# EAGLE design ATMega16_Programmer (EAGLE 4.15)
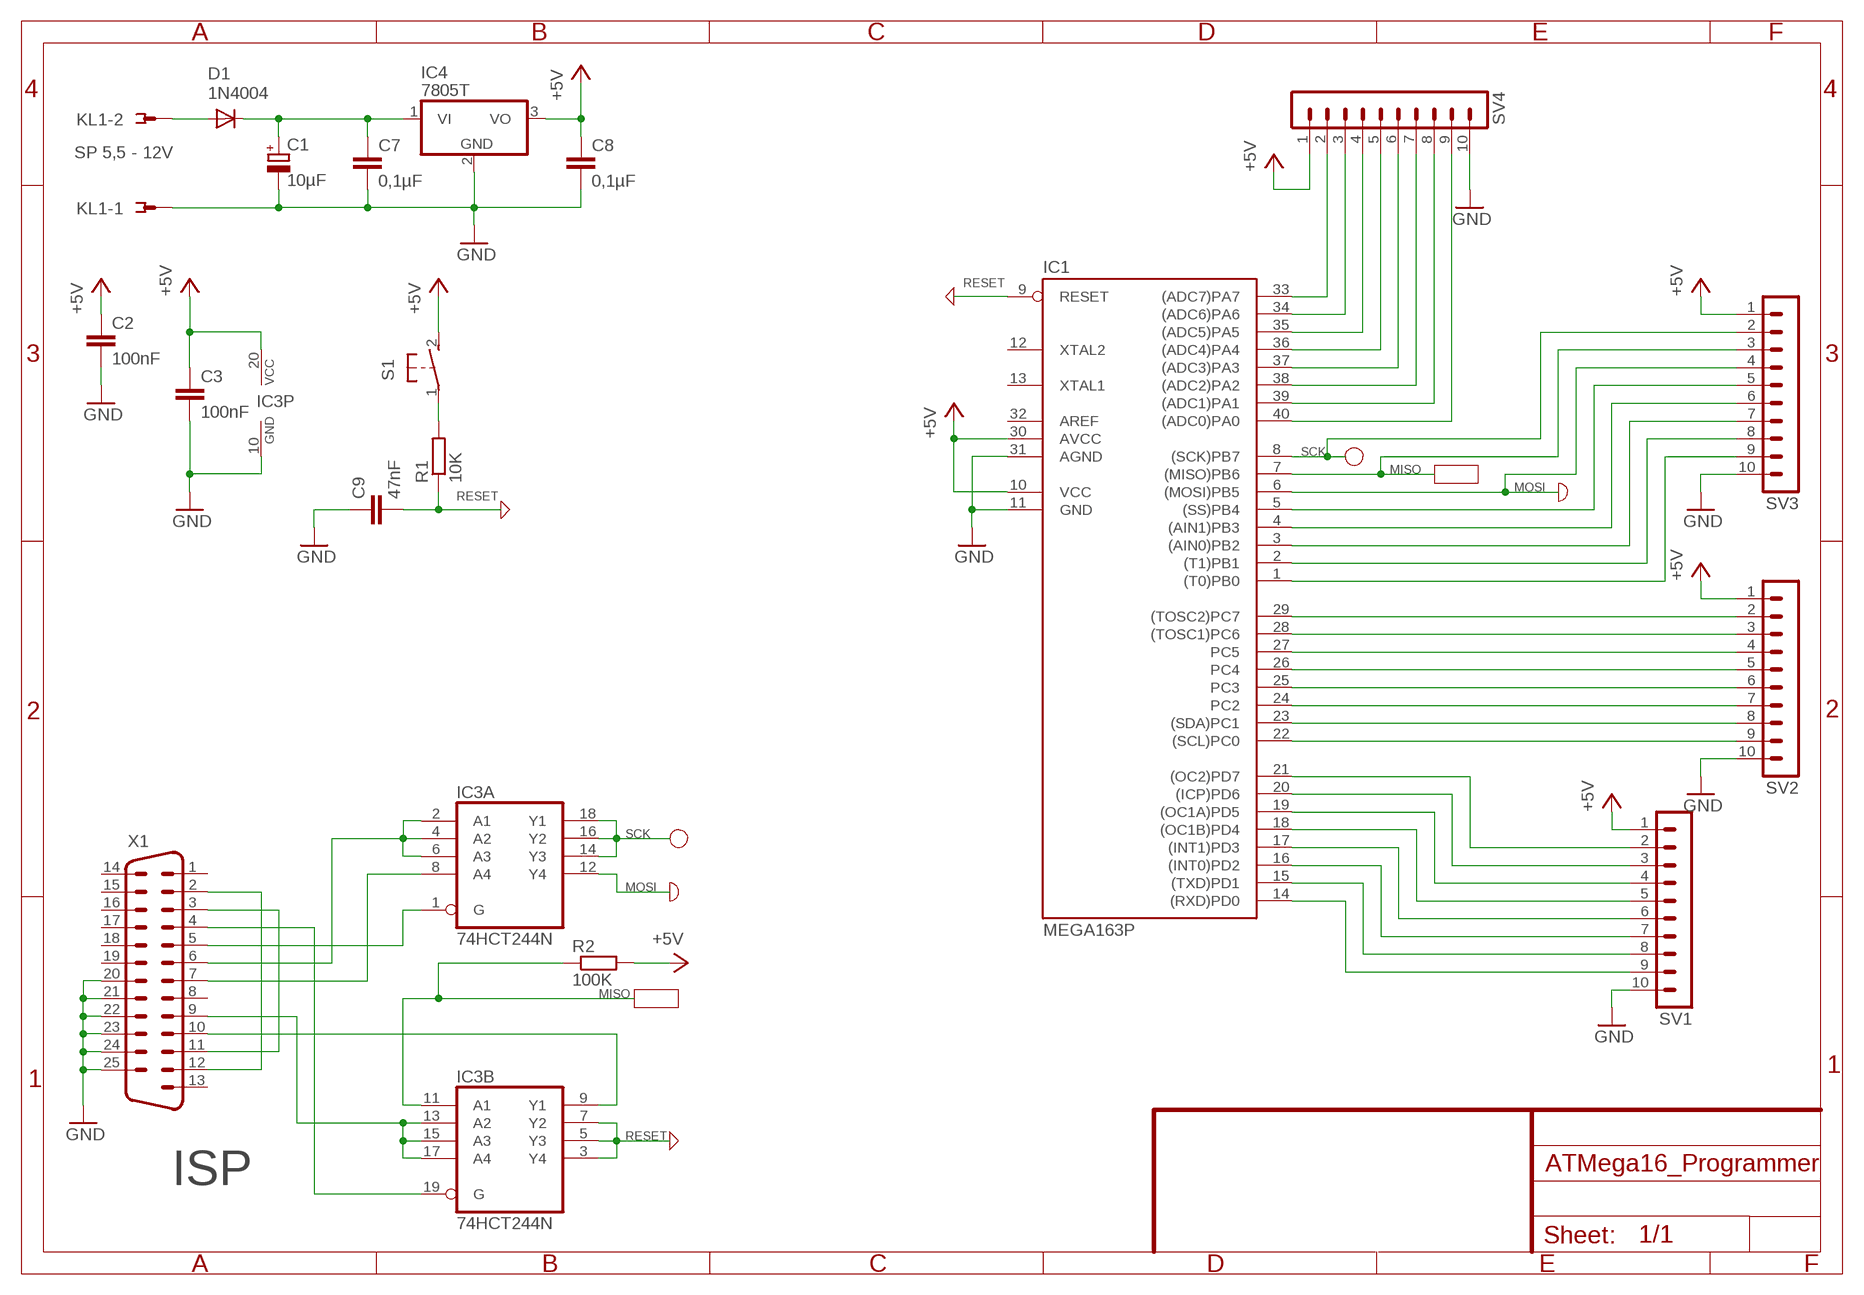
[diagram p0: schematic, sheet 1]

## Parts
C1  10µF  CPOL-EU  [E2-4-RASTERMAß!]
C2  100nF  C-EU050-025X075  [C050-025X075]
C3  100nF  C-EU050-025X075  [C050-025X075]
C7  0,1µF  C-EU050-025X075  [C050-025X075]
C8  0,1µF  C-EU050-025X075  [C050-025X075]
C9  47nF  C-EU050-025X075  [C050-025X075]
D1  1N4004  [DO41-10]
IC1  MEGA163P  [DIL40]
IC3  74HCT244N  [DIL20]
IC4  7805T  [TO220H]
KL1  SP 5,5 - 12V  2POL-PHOENIXSCHRAUBKLEMME  [PHOENIXSCHRAUBKLEMME2POL]
R1  10K  R-EU_0207/15  [0207/15]
R2  100K  R-EU_0207/12  [0207/12]
S1  31-XX  [B3F-31XX]
SV1  MA10-1  [MA10-1]
SV2  MA10-1  [MA10-1]
SV3  MA10-1  [MA10-1]
SV4  MA10-1  [MA10-1]
X1  M25HP  [M25HP]

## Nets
GND: C1.K-(-) C2.2 C3.2 C7.2 C8.2 C9.1 IC1.11(GND) IC1.31(AGND) IC3.10(P:GND) IC4.2(GND) KL1.P1 SV1.10 SV2.10 SV3.10 SV4.10 X1.20 X1.21 X1.22 X1.23 X1.24 X1.25
MISO: IC1.7((MISO)PB6) IC3.11(B:A1) R2.1 SV3.3
MOSI: IC1.6((MOSI)PB5) IC3.12(A:Y4) SV3.4
N$1: C1.K+(+) C7.1 D1.C IC4.1(VI)
N$2: D1.A KL1.P2
N$3: R1.2 S1.1(P)
N$5: X1.2 X1.12
N$6: X1.3 X1.11
N$7: IC3.9(B:Y1) X1.10
N$9: IC3.13(B:A2) IC3.15(B:A3) IC3.17(B:A4) X1.9
N$10: IC3.8(A:A4) X1.7
N$11: IC3.2(A:A1) IC3.4(A:A2) IC3.6(A:A3) X1.6
N$12: IC3.1(A:G) X1.5
N$13: IC3.19(B:G) X1.4
N$15: IC1.21((OC2)PD7) SV1.2
N$16: IC1.20((ICP)PD6) SV1.3
N$17: IC1.19((OC1A)PD5) SV1.4
N$18: IC1.18((OC1B)PD4) SV1.5
N$19: IC1.17((INT1)PD3) SV1.6
N$20: IC1.16((INT0)PD2) SV1.7
N$21: IC1.15((TXD)PD1) SV1.8
N$22: IC1.14((RXD)PD0) SV1.9
N$23: IC1.22((SCL)PC0) SV2.9
N$24: IC1.23((SDA)PC1) SV2.8
N$25: IC1.24(PC2) SV2.7
N$26: IC1.25(PC3) SV2.6
N$27: IC1.26(PC4) SV2.5
N$28: IC1.27(PC5) SV2.4
N$29: IC1.28((TOSC1)PC6) SV2.3
N$30: IC1.29((TOSC2)PC7) SV2.2
N$31: IC1.33((ADC7)PA7) SV4.2
N$32: IC1.34((ADC6)PA6) SV4.3
N$33: IC1.35((ADC5)PA5) SV4.4
N$34: IC1.36((ADC4)PA4) SV4.5
N$35: IC1.37((ADC3)PA3) SV4.6
N$36: IC1.38((ADC2)PA2) SV4.7
N$37: IC1.39((ADC1)PA1) SV4.8
N$38: IC1.40((ADC0)PA0) SV4.9
N$40: IC1.5((SS)PB4) SV3.5
N$41: IC1.4((AIN1)PB3) SV3.6
N$42: IC1.3((AIN0)PB2) SV3.7
N$43: IC1.2((T1)PB1) SV3.8
N$44: IC1.1((T0)PB0) SV3.9
RESET: C9.2 IC1.9(RESET) IC3.3(B:Y4) IC3.5(B:Y3) IC3.7(B:Y2) R1.1
SCK: IC1.8((SCK)PB7) IC3.14(A:Y3) IC3.16(A:Y2) IC3.18(A:Y1) SV3.2
VCC: C2.1 C3.1 C8.1 IC1.10(VCC) IC1.30(AVCC) IC3.20(P:VCC) IC4.3(VO) R2.2 S1.2(S) SV1.1 SV2.1 SV3.1 SV4.1 ; supply symbol labelled +5V
Unconnected: IC1.12(XTAL2) IC1.13(XTAL1) X1.1 X1.8 X1.13 X1.14 X1.15 X1.16 X1.17 X1.18 X1.19 X1.G1 X1.G2

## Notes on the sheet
- RESET
- SCK
- MISO
- MOSI
- RESET
- SCK
- MOSI
- MISO
- RESET
- ISP

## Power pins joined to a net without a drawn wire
AREF: IC1.32(AREF)

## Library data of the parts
C1 = rcl:CPOL-EU: POLARIZED CAPACITOR, European symbol
C2 C3 C7-C9 = rcl:C-EU: CAPACITOR, European symbol
D1 = diode:1N4004: DIODE
IC1 = atmel:MEGA163*P: MICROCONTROLLER 16 Kbytes FLASH, 1 Kbytes EEPROM 1 Kbytes SRAM UART 8-channel 10 bit ADC hardware multiplier
IC3 = 74xx-eu:74*244: Octal BUFFER and LINE DRIVER, 3-state
IC4 = linear:78*: Positive VOLTAGE REGULATOR Source: http://cache.national.com/ds/LM/LM78L05.pdf http://www.fairchildsemi.com/ds/LM/LM7805.pdf
KL1 = Swissphone_Standartbauteile:2POL-PHOENIXSCHRAUBKLEMME
R1 R2 = rcl:R-EU_: RESISTOR, European symbol
S1 = switch-omron:31-XX: OMRON SWITCH
SV1-SV4 = con-lstb:MA10-1: PIN HEADER
X1 = con-subd:M25HP: SUB-D

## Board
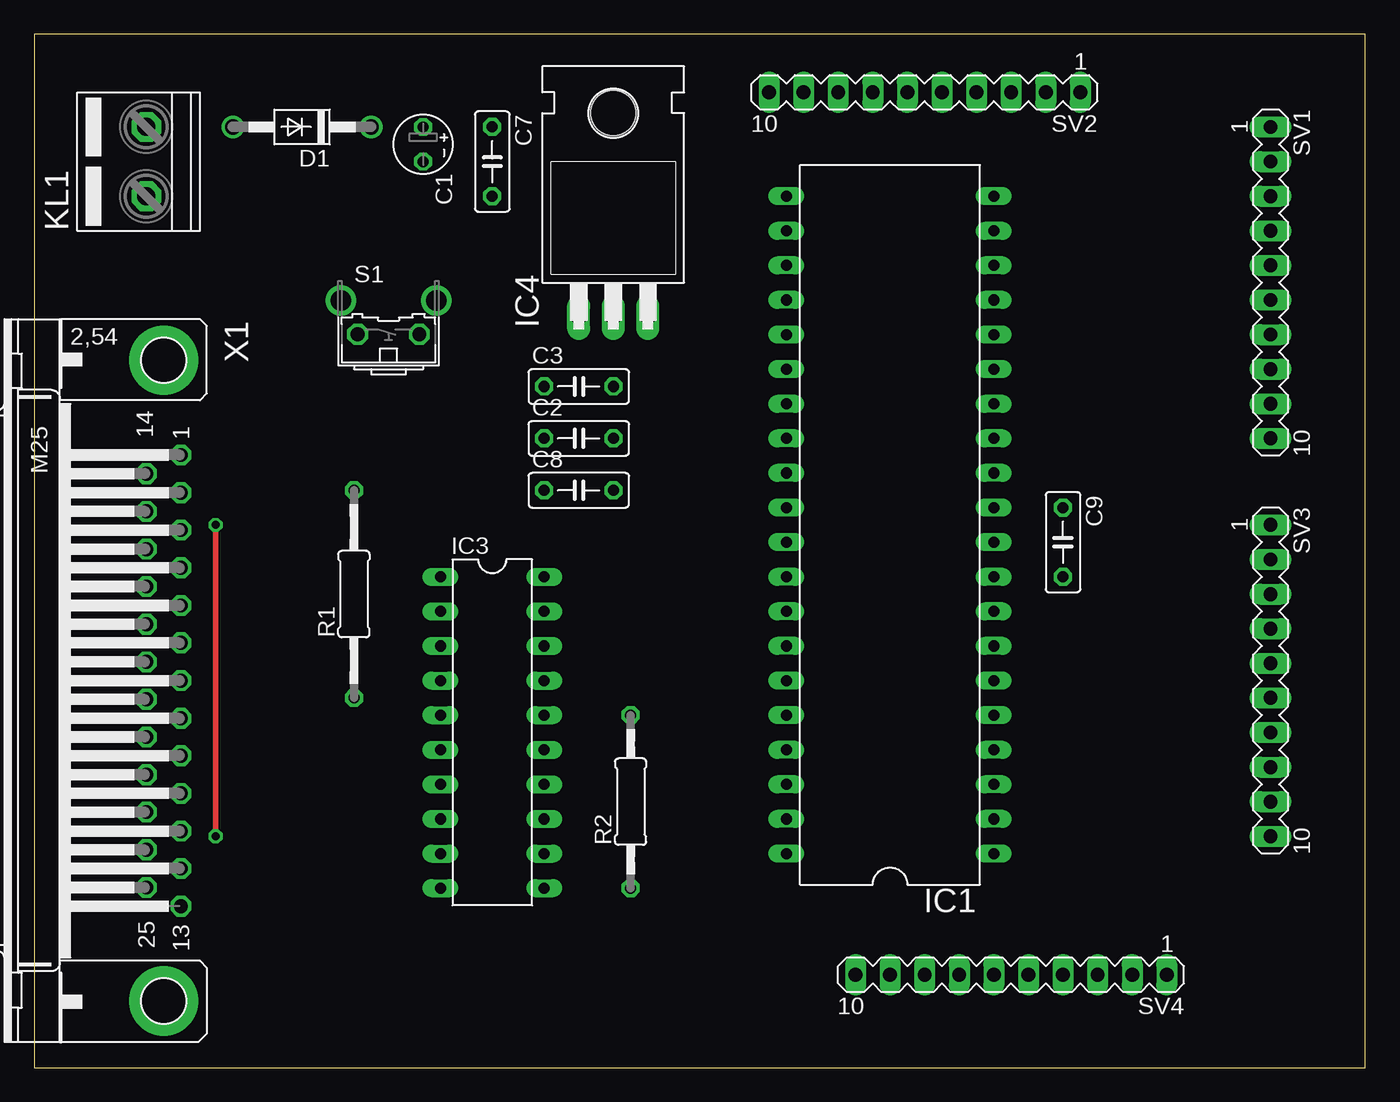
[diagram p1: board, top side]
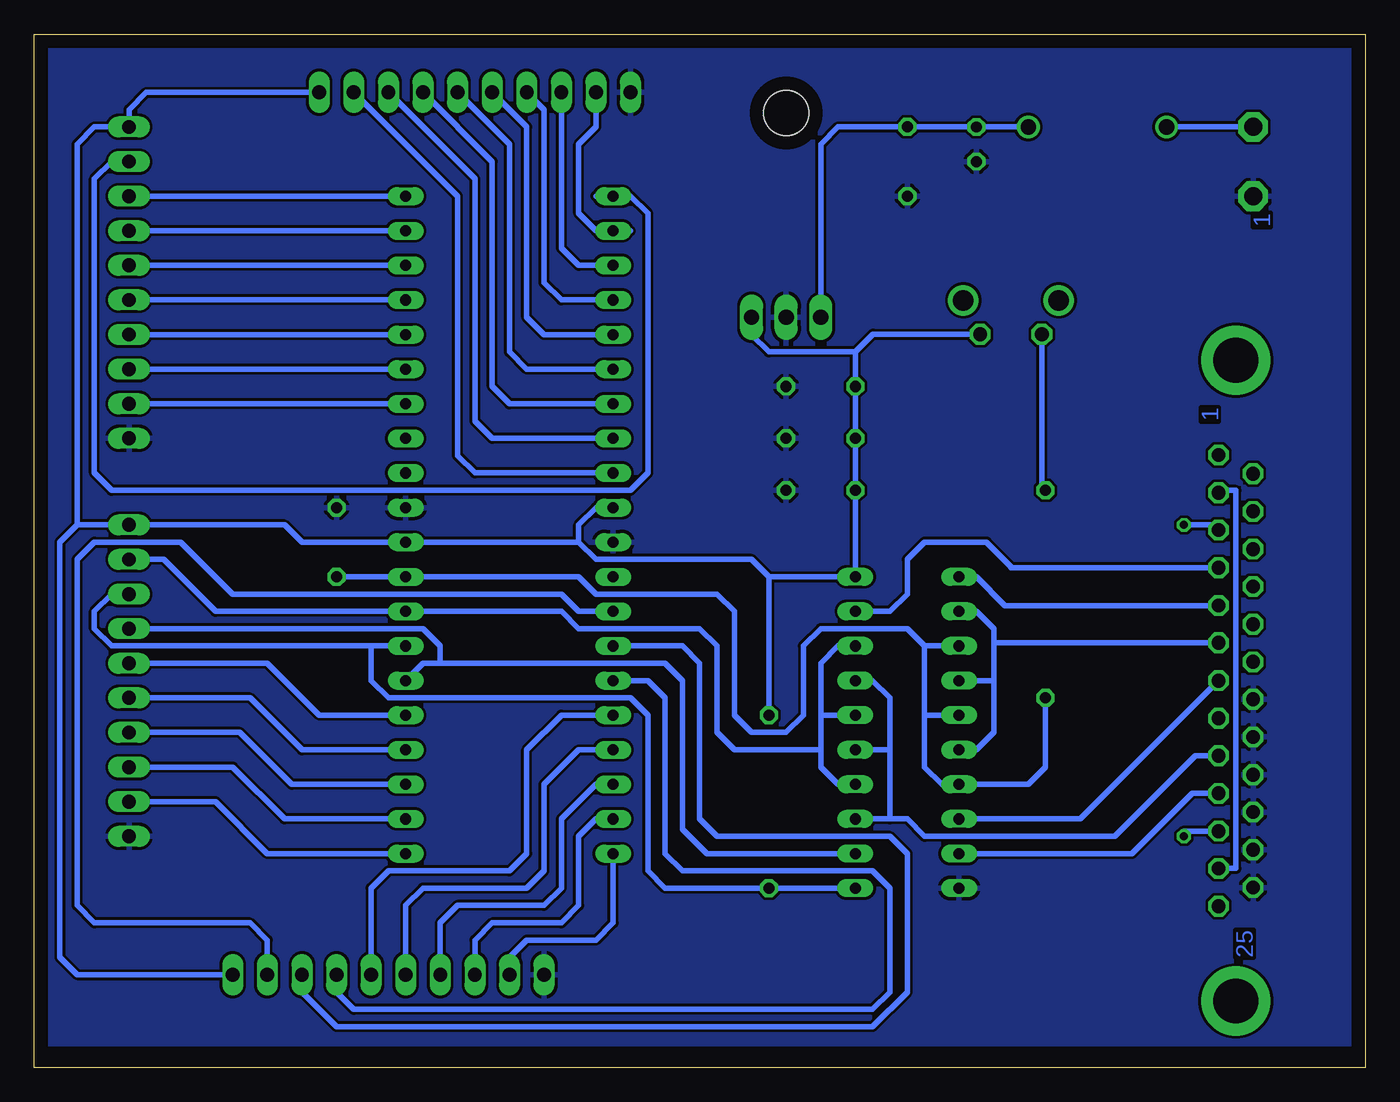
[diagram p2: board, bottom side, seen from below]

Size 97.77 x 75.87 mm. Coordinates in mm from the lower left corner, seen from the top.
Outline: 0,0 97.77,0 97.77,75.87 0,75.87 0,0
Copper layers (1*16): Top 0.035mm / dielectric 1.5mm / Bottom 0.035mm
Design rules "default": minimum track width 10mil, minimum drill 24mil, track to track 8mil, track to pad 8mil, pad to pad 8mil, via to via 8mil, smd to smd 8mil, copper to edge 40mil, drill to drill 8mil, minimum pad ring 10mil, minimum via ring 8mil, stop-mask expansion 4mil, vias tented up to drill 0mil, thermal gap 10mil

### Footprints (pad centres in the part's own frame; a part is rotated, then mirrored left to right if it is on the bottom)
E2-4-RASTERMAß! = drill 0.8 octagon: K+ -1.27,0; K- 1.27,0
C050-025X075 = drill 0.813 octagon: 1 -2.54,0; 2 2.54,0
DO41-10 = drill 1.118 round: A 5.08,0; C -5.08,0
DIL40 = drill 0.813 long: 1 -24.13,-7.62; 2 -21.59,-7.62; 3 -19.05,-7.62; 4 -16.51,-7.62; 5 -13.97,-7.62; 6 -11.43,-7.62; 7 -8.89,-7.62; 8 -6.35,-7.62; 9 -3.81,-7.62; 10 -1.27,-7.62; 11 1.27,-7.62; 12 3.81,-7.62; 13 6.35,-7.62; 14 8.89,-7.62; 15 11.43,-7.62; 16 13.97,-7.62; 17 16.51,-7.62; 18 19.05,-7.62; 19 21.59,-7.62; 20 24.13,-7.62; 21 24.13,7.62; 22 21.59,7.62; 23 19.05,7.62; 24 16.51,7.62; 25 13.97,7.62; 26 11.43,7.62; 27 8.89,7.62; 28 6.35,7.62; 29 3.81,7.62; 30 1.27,7.62; 31 -1.27,7.62; 32 -3.81,7.62; 33 -6.35,7.62; 34 -8.89,7.62; 35 -11.43,7.62; 36 -13.97,7.62; 37 -16.51,7.62; 38 -19.05,7.62; 39 -21.59,7.62; 40 -24.13,7.62
DIL20 = drill 0.813 long: 1 -11.43,-3.81; 2 -8.89,-3.81; 3 -6.35,-3.81; 4 -3.81,-3.81; 5 -1.27,-3.81; 6 1.27,-3.81; 7 3.81,-3.81; 8 6.35,-3.81; 9 8.89,-3.81; 10 11.43,-3.81; 11 11.43,3.81; 12 8.89,3.81; 13 6.35,3.81; 14 3.81,3.81; 15 1.27,3.81; 16 -1.27,3.81; 17 -3.81,3.81; 18 -6.35,3.81; 19 -8.89,3.81; 20 -11.43,3.81
TO220H = drill 1.118 long: 1 -2.54,-10.16; 2 0,-10.16; 3 2.54,-10.16 | hole 3.302: 0,4.826
PHOENIXSCHRAUBKLEMME2POL = drill 1.321 pad 2.184 octagon: P1 2.54,3.81; P2 7.62,3.81
0207/15 = drill 0.813 octagon: 1 -7.62,0; 2 7.62,0
0207/12 = drill 0.813 octagon: 1 -6.35,0; 2 6.35,0
B3F-31XX = drill 1.016 octagon: 1 -2.261,-1.245; 2 2.261,-1.245 | drill 1.499 pad 2.159 round: 3 -3.505,1.245; 4 3.505,1.245
MA10-1 = drill 1.016 long: 1 -11.43,0; 2 -8.89,0; 3 -6.35,0; 4 -3.81,0; 5 -1.27,0; 6 1.27,0; 7 3.81,0; 8 6.35,0; 9 8.89,0; 10 11.43,0
M25HP = drill 1.016 octagon: 1 -16.561,1.27; 2 -13.792,1.27; 3 -11.049,1.27; 4 -8.28,1.27; 5 -5.512,1.27; 6 -2.769,1.27; 7 0,1.27; 8 2.769,1.27; 9 5.512,1.27; 10 8.28,1.27; 11 11.049,1.27; 12 13.792,1.27; 13 16.561,1.27; 14 -15.189,-1.27; 15 -12.421,-1.27; 16 -9.652,-1.27; 17 -6.909,-1.27; 18 -4.14,-1.27; 19 -1.372,-1.27; 20 1.372,-1.27; 21 4.14,-1.27; 22 6.909,-1.27; 23 9.652,-1.27; 24 12.421,-1.27; 25 15.189,-1.27 | drill 3.302 pad 5.08 round: G1 -23.52,0; G2 23.52,0

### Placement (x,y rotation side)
C1  28.57,67.78 270 top
C2  40,46.19 0 top
C3  40,50 0 top
C7  33.65,66.51 270 top
C8  40,42.38 0 top
C9  75.56,38.57 270 top
D1  19.68,69.05 180 top
IC1  62.86,39.84 90 top
IC3  33.65,24.6 270 top
IC4  42.54,65.24 0 top
KL1  12.06,61.43 90 top
R1  23.49,34.76 90 top
R2  43.81,19.52 90 top
S1  26.03,55.08 0 top
SV1  90.8,57.62 270 top
SV2  65.4,71.59 180 top
SV3  90.8,28.41 270 top
SV4  71.75,6.82 180 top
X1  9.52,28.41 270 top

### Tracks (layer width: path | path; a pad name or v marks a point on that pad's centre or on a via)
GND
  pour Bottom: 0.63,1.74 97.15,1.74 97.15,75.4 0.63,75.4
MISO
  Bottom 0.406: IC3.11 R2.1 51.43,13.17 52.7,14.44 52.7,25.87 53.97,27.14 71.75,27.14 73.02,28.41 73.02,30.95 | 71.75,30.95 IC1.7 73.02,30.95 | SV3.3 92.07,34.76 93.34,33.49 93.34,32.22 92.07,30.95 73.02,30.95
MOSI
  Bottom 0.406: 67.94,29.68 69.21,29.68 IC1.6 | 67.94,29.68 67.94,30.95 69.21,32.22 SV3.4 | 67.94,29.68 51.43,29.68 50.16,28.41 50.16,17.51 48.36,15.71 IC3.12
N$1
  Bottom 0.406: D1.C C1.K+ C7.1 38.73,69.05 40,67.78 IC4.1
N$2
  Bottom 0.406: KL1.P2 D1.A
N$3
  Bottom 0.406: S1.1 23.77,42.66 R1.2
N$5
  Bottom 0.406: X1.12 9.52,14.62 9.52,42.38 10.79,42.38 X1.2
N$6  (via drill 0.6)
  Top 0.406: v13.33,16.98 v13.33,39.84
  Bottom 0.406: X1.11 13.33,17.36 v13.33,16.98 | X1.3 10.79,39.84 v13.33,39.84
N$7
  Bottom 0.406: X1.10 12.72,20.13 17.14,15.71 IC3.9
N$8  (via drill 0.6)
  other vias: 13.33,16.98
N$9
  Bottom 0.406: 34.92,18.25 33.65,18.25 32.38,16.98 18.41,16.98 12.49,22.9 X1.9 | 34.92,18.25 IC3.13 | 34.92,18.25 34.92,23.33 | 34.92,23.33 34.92,27.14 36.19,28.41 IC3.17 | 34.92,23.33 IC3.15
N$10
  Bottom 0.406: X1.7 20.95,18.25 IC3.8
N$11
  Bottom 0.406: 27.3,28.41 27.3,24.6 28.57,23.33 IC3.6 | 27.3,28.41 IC3.4 | 27.3,30.95 27.3,28.41 | 27.3,30.95 27.3,32.22 28.57,33.49 IC3.2 | X1.6 27.3,31.18 27.3,30.95
N$12
  Bottom 0.406: X1.5 26.46,33.92 28.57,36.03 IC3.1
N$13
  Bottom 0.406: X1.4 26.03,36.69 26.03,36.77 27.83,38.57 32.38,38.57 33.65,37.3 33.65,34.76 34.92,33.49 IC3.19
N$14  (via drill 0.6)
  other vias: 13.33,39.84
N$15
  Bottom 0.406: 56.51,63.97 IC1.21 53.97,63.97 52.7,62.7 52.7,43.65 53.97,42.38 92.07,42.38 93.34,43.65 93.34,65.24 92.07,66.51 SV1.2
N$16
  Bottom 0.406: IC1.20 SV1.3
N$17
  Bottom 0.406: IC1.19 SV1.4
N$18
  Bottom 0.406: IC1.18 SV1.5
N$19
  Bottom 0.406: IC1.17 SV1.6
N$20
  Bottom 0.406: IC1.16 SV1.7
N$21
  Bottom 0.406: IC1.15 SV1.8
N$22
  Bottom 0.406: IC1.14 SV1.9
N$23
  Bottom 0.406: 53.97,61.43 IC1.22 56.51,61.43 57.78,62.7 57.78,67.78 56.51,69.05 SV2.9
N$24
  Bottom 0.406: IC1.23 57.78,58.89 59.05,60.16 SV2.8
N$25
  Bottom 0.406: IC1.24 59.05,56.35 60.32,57.62 60.32,70.32 SV2.7
N$26
  Bottom 0.406: IC1.25 60.32,53.81 61.59,55.08 61.59,69.05 SV2.6
N$27
  Bottom 0.406: IC1.26 61.59,51.27 62.86,52.54 62.86,67.78 SV2.5
N$28
  Bottom 0.406: IC1.27 62.86,48.73 64.13,50 64.13,66.51 SV2.4
N$29
  Bottom 0.406: IC1.28 64.13,46.19 65.4,47.46 65.4,65.24 SV2.3
N$30
  Bottom 0.406: IC1.29 65.4,43.65 66.67,44.92 66.67,63.97 SV2.2
N$31
  Bottom 0.406: IC1.33 57.78,33.49 59.05,34.76 83.18,34.76 86.99,38.57 93.34,38.57 94.61,37.3 94.61,11.9 93.34,10.63 81.91,10.63 80.64,9.36 SV4.2
N$32
  Bottom 0.406: IC1.34 50.16,30.95 48.89,29.68 48.89,18.25 47.62,16.98 34.92,16.98 33.65,15.71 33.65,5.55 36.19,3.01 75.56,3.01 78.1,5.55 SV4.3
N$33
  Bottom 0.406: IC1.35 52.7,28.41 51.43,27.14 51.43,15.71 50.16,14.44 36.19,14.44 34.92,13.17 34.92,5.55 36.19,4.28 74.29,4.28 75.56,5.55 SV4.4
N$34
  Bottom 0.406: IC1.36 59.05,25.87 61.59,23.33 61.59,15.71 62.86,14.44 71.75,14.44 73.02,13.17 SV4.5
N$35
  Bottom 0.406: IC1.37 57.78,23.33 60.32,20.79 60.32,14.44 61.59,13.17 69.21,13.17 70.48,11.9 SV4.6
N$36
  Bottom 0.406: IC1.38 56.51,20.79 59.05,18.25 59.05,13.17 60.32,11.9 66.67,11.9 67.94,10.63 SV4.7
N$37
  Bottom 0.406: IC1.39 56.51,18.25 57.78,16.98 57.78,11.9 59.05,10.63 64.13,10.63 65.4,9.36 SV4.8
N$38
  Bottom 0.406: SV4.9 62.86,8.09 61.59,9.36 56.51,9.36 55.24,10.63 IC1.40
N$40
  Bottom 0.406: IC1.5 76.83,25.87 80.64,29.68 SV3.5
N$41
  Bottom 0.406: IC1.4 78.1,23.33 81.91,27.14 SV3.6
N$42
  Bottom 0.406: IC1.3 78.84,20.79 82.65,24.6 SV3.7
N$43
  Bottom 0.406: IC1.2 79.37,18.25 83.18,22.06 SV3.8
N$44
  Bottom 0.406: IC1.1 80.64,15.71 84.45,19.52 SV3.9
RESET
  Bottom 0.406: R1.1 23.49,22.06 24.76,20.79 IC3.7 31.11,20.79 32.38,22.06 32.38,25.87 | 32.38,25.87 32.38,30.95 | 32.38,30.95 IC3.3 | 32.38,25.87 IC3.5 | 32.38,30.95 33.65,32.22 40,32.22 41.27,30.95 41.27,25.87 42.54,24.6 45.08,24.6 46.35,25.87 46.35,33.49 47.62,34.76 56.51,34.76 57.78,36.03 IC1.9 C9.2
SCK
  Bottom 0.406: 40,25.87 40,29.68 38.73,30.95 IC3.18 | 40,25.87 IC3.16 | IC3.14 38.73,20.79 40,22.06 40,23.33 | 40,23.33 40,25.87 | 40,23.33 46.35,23.33 47.62,24.6 47.62,30.95 48.89,32.22 57.78,32.22 59.05,33.49 IC1.8 84.45,33.49 88.26,37.3 SV3.2
VCC
  Bottom 0.406: S1.2 36.16,53.84 37.46,52.54 | IC1.30 56.51,41.11 57.78,39.84 57.78,38.57 | 37.46,52.54 43.81,52.54 45.08,53.81 IC4.3 | 37.46,52.54 C3.1 C2.1 C8.1 IC3.20 43.81,36.03 | R2.2 43.81,36.03 | 43.81,36.03 45.08,37.3 56.51,37.3 57.78,38.57 | 57.78,38.57 IC1.10 78.1,38.57 79.37,39.84 SV3.1 94.61,39.84 | 94.61,39.84 94.61,67.78 93.34,69.05 SV1.1 90.8,70.32 89.53,71.59 SV2.1 | SV4.1 94.61,6.82 95.88,8.09 95.88,38.57 94.61,39.84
